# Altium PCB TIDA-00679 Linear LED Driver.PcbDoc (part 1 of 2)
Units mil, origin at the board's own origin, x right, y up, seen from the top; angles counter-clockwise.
Board outline 4400 x 2430 mil, 2 copper layers (Top Layer, Bottom Layer), stack 62 mil thick; 157 components, 72 nets, 421 pads, 393 vias.
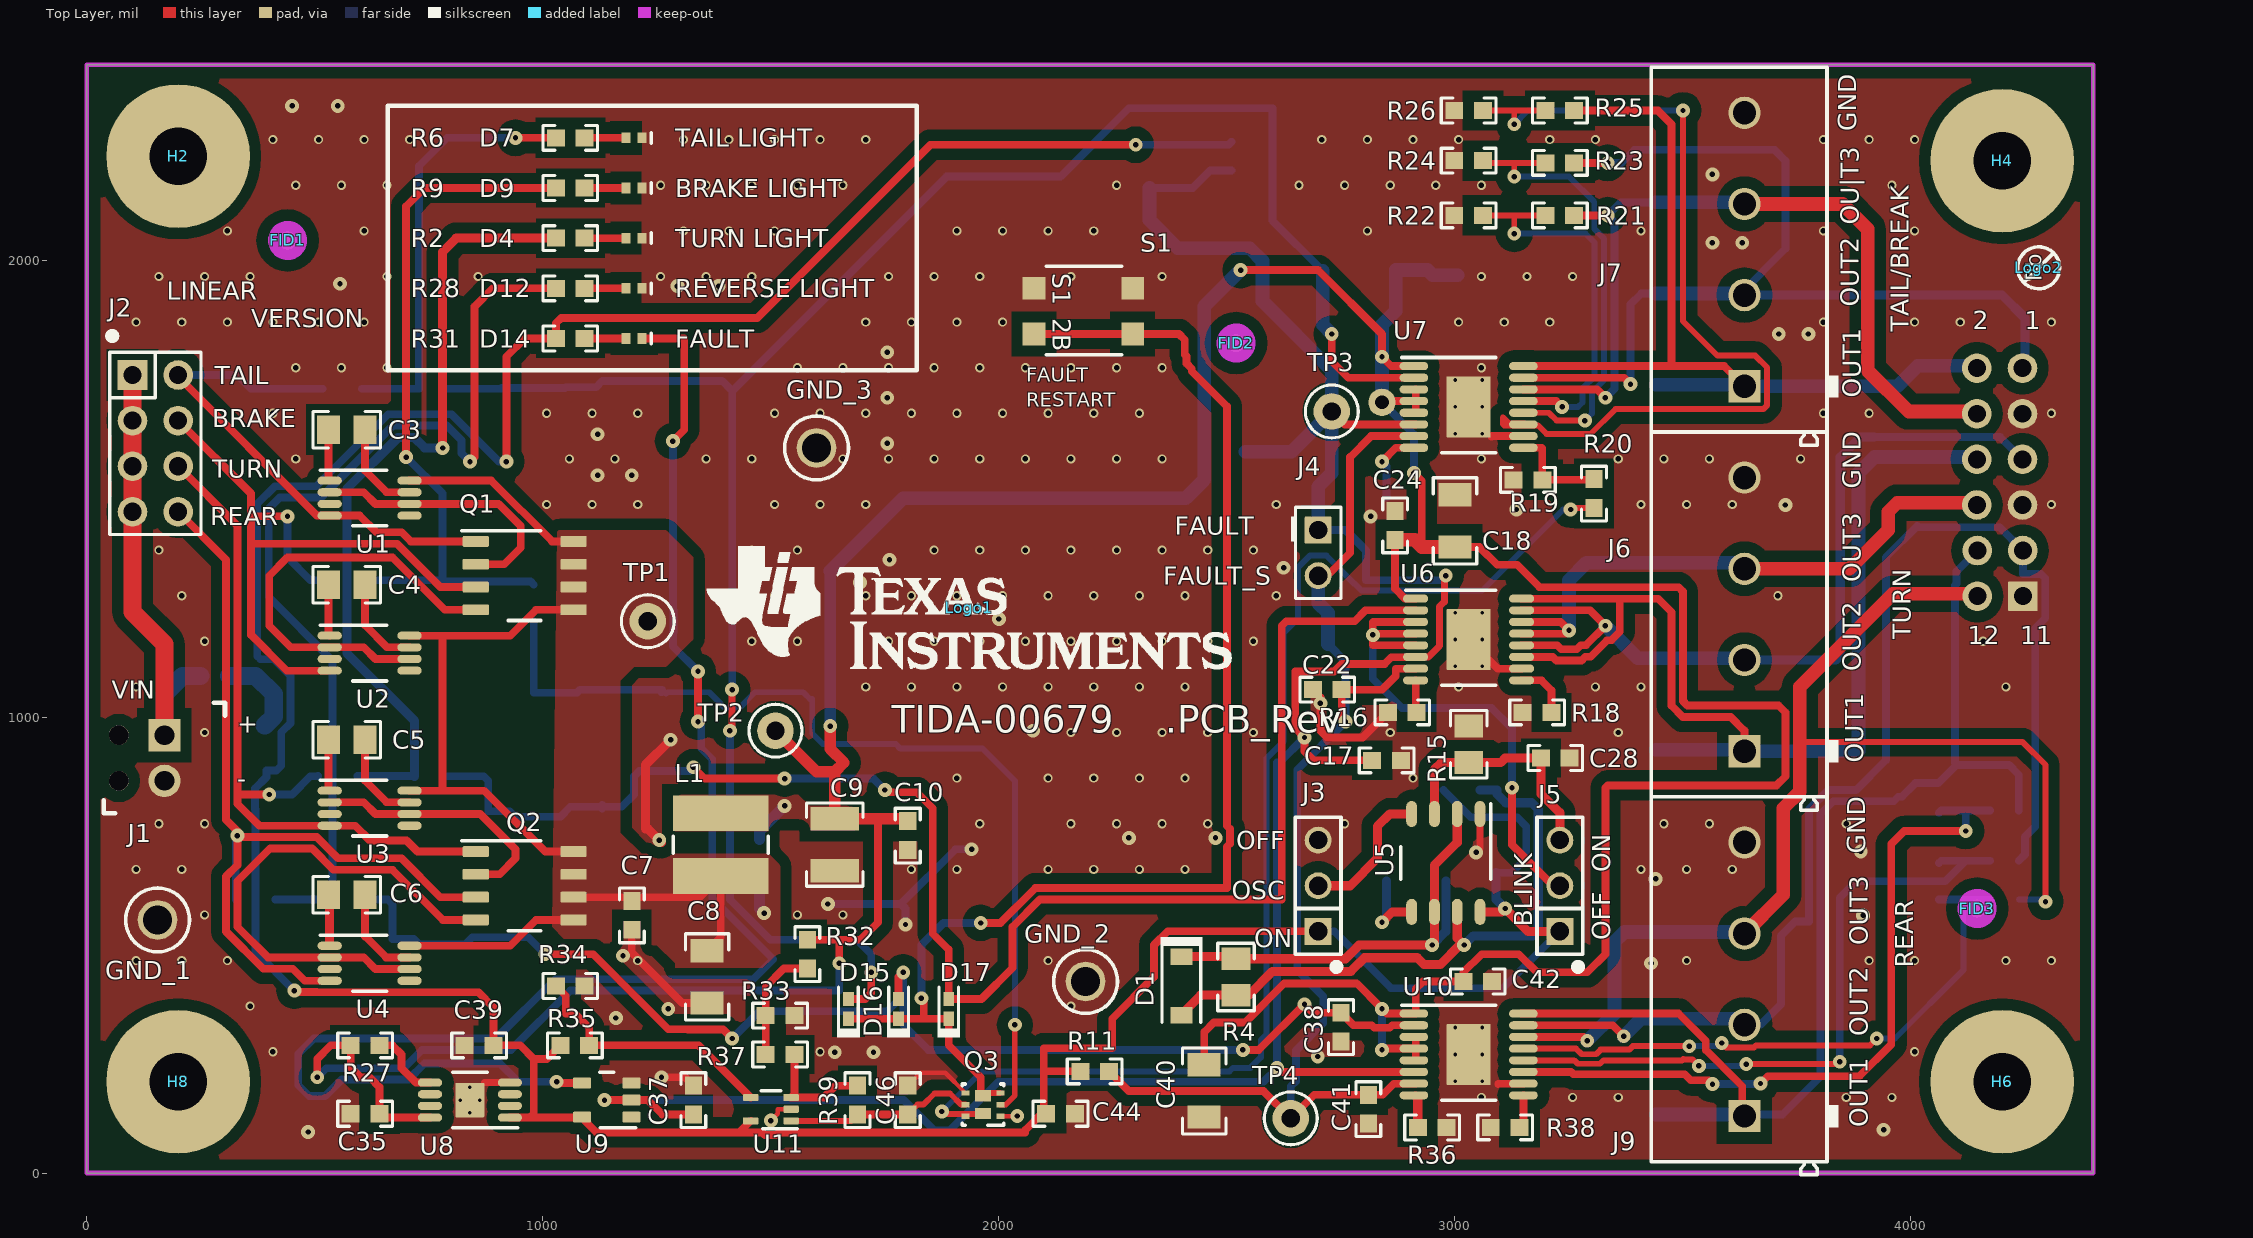
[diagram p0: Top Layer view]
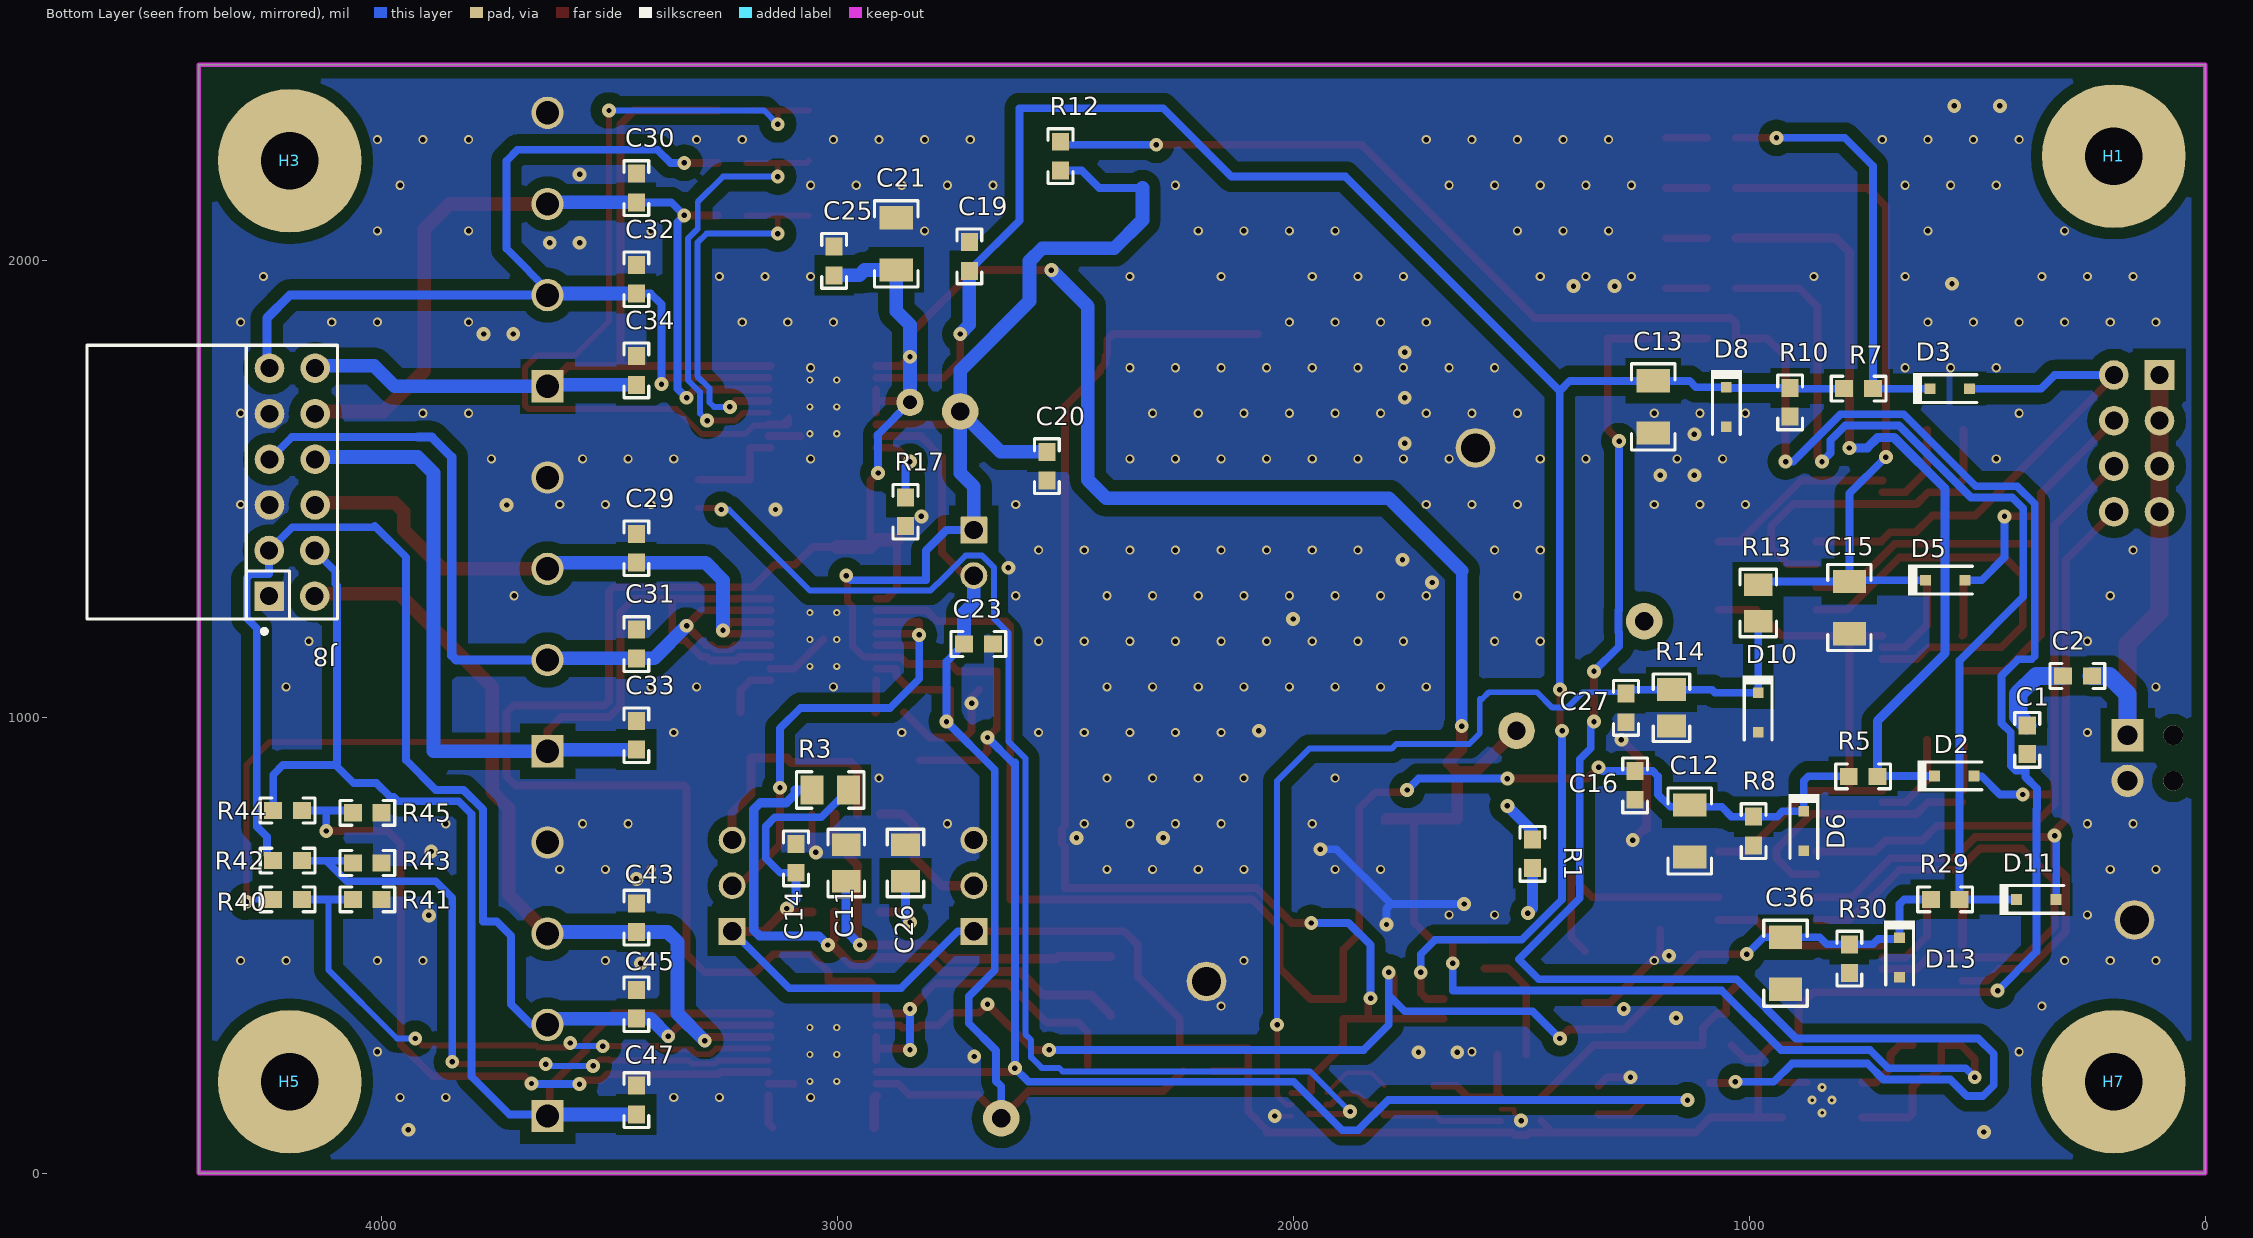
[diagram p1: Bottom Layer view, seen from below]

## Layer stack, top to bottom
Top Solder: solder mask 0.4, Solder Resist, Dk 3.5
Top Layer: signal copper 1.4
Dielectric1: core 59.2, FR-4, Dk 4.8
Bottom Layer: signal copper 1.4
Bottom Solder: solder mask 0.4, Solder Resist, Dk 3.5

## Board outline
0,0 4400,0 4400,2430 0,2430

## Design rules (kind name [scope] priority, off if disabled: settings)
AcuteAngle [All] p1: minimum=4.50000000000000E+0001 checktracksonly=FALSE
AssemblyTestPointUsage [All] p1: valid=2
Clearance Clearance_Keepouts [((IsTrack Or IsArc) And Not InPoly) And IsFree and IsKeepOut vs ((IsTrack Or IsArc) And Not InPoly) And IsFree and IsKeepOut] p1: gap=0
Clearance Clearance_BoardEdge_MountingHoles [OnCopper and InComponentClass('Mounting Holes') vs IsKeepOut] p2: gap=30
Clearance Clearance_BoardEdge_Poly [OnCopper and InPoly vs IsKeepOut] p3: gap=25
Clearance Clearance_BoardEdge [OnCopper and Not InComponentClass('Logo') and not InComponentClass('FiducialMark') and not InRegion(1000,500,4000,800) and Not IsKeepout vs IsKeepOut] p4: gap=60
Clearance Clearance_Poly [InPolygon] p5: gap=25
Clearance [All] p6: gap=7.87
ComponentClearance ComponentClearance_MountingHoles_FiducialMarks [InComponentClass('Mounting Holes') vs InComponentClass('FiducialMark')] p1: gap=50 collisioncheckmode=3 verticalgap=10 showdistances=FALSE
ComponentClearance ComponentClearance_Shunt [InComponentClass('Header') vs InComponentClass('Shunt')] p2: gap=0 collisioncheckmode=3 verticalgap=0 showdistances=FALSE
ComponentClearance ComponentClearance_Logo [InComponentClass('Logo')] p3: gap=50 collisioncheckmode=3 verticalgap=10 showdistances=FALSE
ComponentClearance ComponentClearance_ScrewToNut [(HasFootprint('NY PMS 440 0025 PH')) vs (HasFootprint('Keystone_1902C'))] p4: gap=5 collisioncheckmode=3 verticalgap=10 showdistances=FALSE
ComponentClearance ComponentClearance_MountingHoles [InComponentClass('Mounting Holes')] p5: gap=30 collisioncheckmode=3 verticalgap=100000 showdistances=FALSE
ComponentClearance ComponentClearance_SmallPassives [HasFootprint('0201*') or HasFootprint('0402*') or HasFootprint('0508') or HasFootprint('0603*') or HasFootprint('0612') or HasFootprint('0805*') or HasFootprint('0815*') or HasFootprint('0830*') or HasFootprint('1206*') or HasFootprint('1210*') or HasFootprint('1808*') or HasFootprint('1812*') or HasFootprint('1825*') or HasFootprint('2010*') or HasFootprint('2220*') or HasFootprint('2225*') or HasFootprint('2512*') or HasFootprint('2728*') or HasFootprint('3518*') vs HasFootprint('0201*') or HasFootprint('0402*') or HasFootprint('0508') or HasFootprint('0603*') or HasFootprint('0612') or HasFootprint('0805*') or HasFootprint('0815*') or HasFootprint('0830*') or HasFootprint('1206*') or HasFootprint('1210*') or HasFootprint('1808*') or HasFootprint('1812*') or HasFootprint('1825*') or HasFootprint('2010*') or HasFootprint('2220*') or HasFootprint('2225*') or HasFootprint('2512*') or HasFootprint('2728*') or HasFootprint('3518*')] p6: gap=20 collisioncheckmode=3 verticalgap=10 showdistances=FALSE
ComponentClearance ComponentClearance_THtoSMT [IsThruComponent vs IsSMTComponent] p7: gap=100 collisioncheckmode=3 verticalgap=30 showdistances=FALSE
ComponentClearance ComponentClearance_THtoTH [IsThruComponent vs IsThruComponent] p8: gap=0 collisioncheckmode=3 verticalgap=0 showdistances=TRUE
ComponentClearance [All] p9: gap=40 collisioncheckmode=3 verticalgap=10 showdistances=FALSE
DiffPairsRouting [All] p1: maxlimit=100 minlimit=10 mostfreqgap=10 toplayer_minwidth=15 toplayer_maxwidth=15 toplayer_prefwidth=15 bottomlayer_minwidth=15 bottomlayer_maxwidth=15 bottomlayer_prefwidth=15 maxuncoupledlength=1000
FabricationTestPointUsage TestPointUsage [All] p1: valid=2 allowmultiple=FALSE
FabricationTestpoint Testpoint [All] p1: side=3 testpointundercomponent=TRUE minsize=40 maxsize=100 preferedsize=60 minholesize=0 maxholesize=40 preferedholesize=32 testpointgrid=1 allowsidetop=TRUE allowsidebottom=TRUE usegrid=TRUE gridtolerance=0.01
FanoutControl Fanout_LCC [IsLCC] p1: bgadir=Out bgaviamode=Centered fanoutstyle=Auto fanoutdirection=Alternating viagrid=1 // Fanout_LCC (Default Rule)
FanoutControl Fanout_BGA [IsBGA] p2: bgadir=Out bgaviamode=Centered fanoutstyle=Auto fanoutdirection=Alternating viagrid=1 // Fanout_BGA (Default Rule)
FanoutControl Fanout_Default [All] p4: bgadir=Out bgaviamode=Centered fanoutstyle=Auto fanoutdirection=Alternating viagrid=1 // Fanout_Default (Default Rule)
FanoutControl Fanout_Small [(CompPinCount < 5)] p5: bgadir=Out bgaviamode=Centered fanoutstyle=Auto fanoutdirection=OutThenIn viagrid=1 // Fanout_Small (Default Rule)
HoleSize [All] p1: absolutevalues=TRUE maxlimit=251 minlimit=7.8 maxpercent=80.000 minpercent=20.000
MinimumAnnularRing MinimumAnnularRing_ThermalPadVias [IsVia and InAnyComponent] p1: minimumring=3
MinimumAnnularRing [All] p2: minimumring=4
MinimumSolderMaskSliver MinimumSolderMaskSliver_Logo [InComponentClass('Logo') vs InComponentClass('Logo')] p1: minsoldermaskwidth=0.7
MinimumSolderMaskSliver [All] p2: minsoldermaskwidth=3.94
PlaneConnect [All] p1: planeconnectstyle=Relief reliefexpansion=10 reliefentries=4 reliefconductorwidth=10 reliefairgap=10
PolygonConnect [All] p1: connectstyle=Direct reliefconductorwidth=10 reliefentries=4 polygonreliefangle="90 Angle" airgapwidth=10
RoutingVias ThermalPadVias [IsVia and InAnyComponent] p1: holewidth=7.8 width=19.68 viastyle="Through Hole" minholewidth=7.8 minwidth=13.8 maxholewidth=12.99 maxwidth=23.62
RoutingVias [All] p2: holewidth=16 width=34 viastyle="Through Hole" minholewidth=7.8 minwidth=20 maxholewidth=40 maxwidth=65
SilkToBoardRegionClearance [Not ((IsComment or IsDesignator) And (Hide <> 'False')) and not InRegion(1000,500,4000,800)] p1:
SilkToSilkClearance SilkToSilkClearance_Pb-FreeLogo [(HasFootprint('Pb-Free_Overlay_Medium') OR HasFootprint('Pb-Free_Overlay_Small')) vs (HasFootprint('Pb-Free_Overlay_Medium') OR HasFootprint('Pb-Free_Overlay_Small'))] p1: silktosilkclearance=0
SilkToSilkClearance [All] p2: silktosilkclearance=0
SilkToSolderMaskClearance SilkToComonentPadClearance [IsPad and InAnycomponent] p1: minsilkscreentomaskgap=0 clearancetoexposedcopper=TRUE
SilkToSolderMaskClearance "Silk to Solder Mask Opening" [All] p2: minsilkscreentomaskgap=0 clearancetoexposedcopper=FALSE
SolderMaskExpansion [All] p1: expansion=1.97
UnpouredPolygon [All] p1: allowunpoured=FALSE
Width [All] p1: maxlimit=100 minlimit=6 preferedwidth=10 checkconnectedcopper=TRUE
14 further rules are at their usual default settings.

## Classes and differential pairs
component class "Mounting Holes": H2 H4 H6 H8
component class Logo: Logo1
component class "TIDA-00679 Linear LED Driver_Hardware": FID1 FID2 FID3 H1 H2 H3 H4 H5 H6 H7 H8 Logo1 Logo2 ZZ1 ZZ2 ZZ3
component class FiducialMark: FID1 FID2 FID3
component class AssemblyNote: ZZ1 ZZ2 ZZ3
component class Header: J2 J3 J4 J5
component class "TIDA-00679 Linear LED Driver 1": C1 C2 C3 C4 C5 C6 C7 C8 C9 C10 J1 J2 L1 Q1 Q2 R1 TP1 TP2 U1 U2 U3 U4
component class "TIDA-00679 Linear LED Driver 2": C11 C12 C13 C14 C15 C16 C17 C18 C19 C20 C21 C22 C23 C24 C25 C26 C27 C28 C29 C30 C31 C32 C33 C34 C35 C36 C37 C38 C39 C40 C41 C42 C43 C44 C45 C46 C47 C56 C60 D1 D2 D3 D4 D5 D6 D7 D8 D9 D10 D11 D12 D13 D14 D15 D16 D17 GND_1 GND_2 GND_3 J3 J4 J5 J6 J7 J8 J9 Q3 R2 R3 R4 R5 R6 R7 R8 R9 R10 R11 R12 R13 R14 R15 R16 R17 R18 R19 R20 R21 R22 R23 R24 R25 R26 R27 R28 R29 R30 R31 R32 R33 R34 R35 R36 R37 R38 R39 R40 R41 R42 R43 R44 R45 S1 TP3 TP4 U5 U6 U7 U8 U9 U10 U11

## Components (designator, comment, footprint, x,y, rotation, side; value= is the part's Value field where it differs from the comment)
C1 "GRM188R71H473KA61D" 0603 390,950 r90 bottom
C2 "GRM188R71H473KA61D" 0603 280,1090 r180 bottom
C3 "C2012X5R1H225K125AB" 0805_HV 570,1630 r180 top
C4 "C2012X5R1H225K125AB" 0805_HV 570,1290 r180 top
C5 "C2012X5R1H225K125AB" 0805_HV 570,950 r180 top
C6 "C2012X5R1H225K125AB" 0805_HV 570,610 r180 top
C7 "GRM188R72A102KA01D" 0603 1195,565 r270 top
C8 "GRM31CR71H475KA12L" 1206 1360,430 r270 top
C9 "GRM32ER71H106KA12L" 1210 1640,720 r270 top
C10 "C1608X7R1H104K080AA" 0603 1800,740 r270 top
C11 "GRM219R71E824KA88D" 0805_HV 2980,680 r90 bottom
C12 "GRM31CR71H475KA12L" 1206 1130,750 r90 bottom
C13 "GRM31CR71H475KA12L" 1206 1210,1680 r90 bottom
C14 "06035C104KAT2A" 0603 3090,690 r270 bottom
C15 "GRM31CR71H475KA12L" 1206 780,1240 r270 bottom
C16 "06035C104KAT2A" 0603 1249.93,850 r90 bottom
C17 "06035C104KAT2A" 0603 2850,905 r0 top
C18 "GRM31CR71H475KA12L" 1206 3000,1430 r270 top
C19 "06035C104KAT2A" 0603 2710,2010 r270 bottom
C20 "06035C104KAT2A" 0603 2540,1550 r270 bottom
C21 "GRM31CR71H475KA12L" 1206 2870,2037.48 r270 bottom
C22 "06035C104KAT2A" 0603 2720,1060 r180 top
C23 "06035C104KAT2A" 0603 2690,1160 r180 bottom
C24 "06035C104KAT2A" 0603 2868.7,1420 r270 top
C25 "06035C104KAT2A" 0603 3006.21,2000 r270 bottom
C26 "0805YC224JAT2A" 0805_HV 2850,680 r90 bottom
C27 "06035C104KAT2A" 0603 1270,1020 r270 bottom
C28 "06031C103JAT2A" 0603 3220,910 r0 top
C29 "06031C103JAT2A" 0603 3440.07,1370 r270 bottom
C30 "06031C103JAT2A" 0603 3440.07,2160 r270 bottom
C31 "06031C103JAT2A" 0603 3440.07,1160 r270 bottom
C32 "06031C103JAT2A" 0603 3440.07,1960 r270 bottom
C33 "06031C103JAT2A" 0603 3440.07,960 r270 bottom
C34 "06031C103JAT2A" 0603 3440,1760 r270 bottom
C35 "C1608X7R1H104K" 0603 610,130 r180 top
C36 "GRM31CR71H475KA12L" 1206 920,460 r90 bottom
C37 "0603YC104JAT2A" 0603 1330,160 r90 top
C38 "06035C104KAT2A" 0603 2750,320 r90 top
C39 "C1608X5R1A226M080AC" 0603 860,280 r180 top
C40 "GRM31CR71H475KA12L" 1206 2450,180 r90 top
C41 "06035C104KAT2A" 0603 2810,140 r270 top
C42 "06035C104KAT2A" 0603 3050,420 r180 top
C43 "06031C103JAT2A" 0603 3440.07,560 r270 bottom
C44 "0603YC104JAT2A" 0603 2135,130 r180 top
C45 "06031C103JAT2A" 0603 3440.07,370 r270 bottom
C46 "0603YC104JAT2A" 0603 1800,160 r270 top
C47 "06031C103JAT2A" 0603 3440.07,160 r270 bottom
D1 "1N4148W-7-F" SOD-123 2400,410 r270 top
D2 "PMEG6010CEJ,115" SOD-323F 550,870.87 r180 bottom
D3 "PMEG6010CEJ,115" SOD-323F 560,1720 r180 bottom
D4 "SML-P12PTT86" SML-P1_GREEN 1200,2050 r180 top
D5 "PMEG6010CEJ,115" SOD-323F 570,1300 r180 bottom
D6 "BZT52C9V1S-7-F" sod-323 880,750 r270 bottom
D7 "SML-P12PTT86" SML-P1_GREEN 1200,2270 r180 top
D8 "BZT52C9V1S-7-F" sod-323 1050,1680 r270 bottom
D9 "SML-P12PTT86" SML-P1_GREEN 1200,2160 r180 top
D10 "MMSZ5229BS-7-F" sod-323 980,1010 r270 bottom
D11 "PMEG6010CEJ,115" SOD-323F 370,600 r180 bottom
D12 "SML-P12PTT86" SML-P1_GREEN 1200,1940 r180 top
D13 "BZT52C9V1S-7-F" sod-323 670,472.8 r270 bottom
D14 "SML-P12UTT86" SML-P1_RED 1200,1830 r180 top
D15 "SBR0220T5-7-F" SOD-523 1670,360 r90 top
D16 "SBR0220T5-7-F" SOD-523 1780,360 r90 top
D17 "SBR0220T5-7-F" SOD-523 1890,360 r90 top
FID1 "Fiducial" Fiducial10-20 440,2045 r0 top
FID2 "Fiducial" Fiducial10-20 2520,1820 r0 top
FID3 "Fiducial" Fiducial10-20 4145.02,580 r0 top
GND_1 "5011" Keystone5011 155,555 r0 top
GND_2 "5011" Keystone5011 2190,420 r0 top
GND_3 "5011" Keystone5011 1600,1590 r0 top
H1 "1902C" Keystone_1902C 200,2230 r180 bottom locked
H2 "NY PMS 440 0025 PH" "NY PMS 440 0025 PH" 200,2230 r0 top locked
H3 "1902C" Keystone_1902C 4200,2220 r180 bottom locked
H4 "NY PMS 440 0025 PH" "NY PMS 440 0025 PH" 4200,2220 r0 top locked
H5 "1902C" Keystone_1902C 4200,200 r180 bottom locked
H6 "NY PMS 440 0025 PH" "NY PMS 440 0025 PH" 4200,200 r0 top locked
H7 "1902C" Keystone_1902C 200,200 r180 bottom locked
H8 "NY PMS 440 0025 PH" "NY PMS 440 0025 PH" 200,200 r0 top locked
J1 "1725656" CONN_1725656 170,910 r270 top
J2 "PEC04DAAN" CONN_PEC04DAAN 150,1600 r270 top
J3 "PEC03SAAN" CONN_PEC03SAAN 2700,630 r90 top
J4 "PEC02SAAN" CONN_PEC02SAAN 2700,1360 r270 top
J5 "PEC03SAAN" CONN_PEC03SAAN 3230,630 r90 top
J6 "1715747" Phoenix_1715747 3634.79,1225 r90 top
J7 "1715747" Phoenix_1715747 3634.79,2025 r90 top
J8 "SSQ-106-02-G-D-RA" SSQ-106-02-G-D-RA 4195,1515 r270 bottom
J9 "1715747" Phoenix_1715747 3634.79,425 r90 top
L1 "74408943022" WE-SPC_4838 1390,720 r90 top
Logo1 "Texas Instruments" TI_Stacked_Overlay_Medium 1935,1240 r0 top
Logo2 "Pb-Free Symbol" Pb-Free_Overlay_Small 4280,1985 r90 top
Q1 "SQ9945BEY-T1-GE3" SOIC-8 960,1310 r0 top
Q2 "SQ9945BEY-T1-GE3" SOIC-8 960,630 r0 top
Q3 "CSD85301Q2" DQK0006B 1965,150 r180 top
R1 "RC0603JR-070RL" 0603 1475,700 r90 bottom
R2 "CRCW06033K30JNEA" 0603 1060,2050 r180 top
R3 "CRCW0805680KJNEA" 0805_HV 3014.61,839.88 r180 bottom
R4 "CRCW0805680KJNEA" 0805_HV 2520,430 r270 top
R5 "RC0603FR-0759KL" 0603 750,870 r0 bottom
R6 "CRCW06033K30JNEA" 0603 1060,2270 r180 top
R7 "RC0603FR-0759KL" 0603 760,1720 r0 bottom
R8 "RC0603FR-0742K2L" 0603 990,750 r90 bottom
R9 "CRCW06033K30JNEA" 0603 1060,2160 r180 top
R10 "RC0603FR-0742K2L" 0603 910,1690 r90 bottom
R11 "CRCW0603100KFKEA" 0603 2210,222.97 r180 top
R12 "CRCW0603100KFKEA" 0603 2509.93,2230 r90 bottom
R13 "CRCW080521K5FKEA" 0805_HV 980,1250 r90 bottom
R14 "CRCW080520K0JNEA" 0805_HV 1170,1020 r90 bottom
R15 "CRCW0805100KFKEA" 0805_HV 3030,940 r270 top
R16 "CRCW06030000Z0EA" 0603 2884.43,1010 r0 top
R17 "CRCW06030000Z0EA" 0603 2850,1450 r90 bottom
R18 "CRCW06031K21FKEA" 0603 3180,1010 r0 top
R19 "CRCW06031K21FKEA" 0603 3160,1520 r0 top
R20 "CRCW06032K43FKEA" 0603 3305,1490 r90 top
R21 "CRCW06030000Z0EA" 0603 3230,2100 r0 top
R22 "CRCW060320K0FKEA" 0603 3030,2100 r0 top
R23 "CRCW06030000Z0EA" 0603 3230,2215 r0 top
R24 "CRCW060320K0FKEA" 0603 3030,2220 r0 top
R25 "CRCW06030000Z0EA" 0603 3230,2330 r0 top
R26 "CRCW060320K0FKEA" 0603 3030,2330 r0 top
R27 "CRCW060310K0FKEA" 0603 610,280 r180 top
R28 "CRCW06033K30JNEA" 0603 1060,1940 r180 top
R29 "RC0603FR-0759KL" 0603 570,600 r0 bottom
R30 "RC0603FR-0742K2L" 0603 780,470 r90 bottom
R31 "RC0603FR-07470RL" 0603 1060,1830 r180 top
R32 "CRCW06035K62FKEA" 0603 1580,480 r90 top
R33 "RC0603FR-07510RL" 0603 1520,345 r180 top
R34 "CRCW060310K0FKEA" 0603 1070,280 r180 top
R35 "CRCW060310K0FKEA" 0603 1060,410 r180 top
R36 "CRCW06030000Z0EA" 0603 2950,100 r180 top
R37 "RC0603FR-072K55L" 0603 1520,260 r0 top
R38 "CRCW06031K21FKEA" 0603 3110,100 r0 top
R39 "RC0603FR-0747KL" 0603 1690,160 r90 top
R40 "CRCW06030000Z0EA" 0603 4205,600 r0 bottom
R41 "CRCW060320K0FKEA" 0603 4030,600 r0 bottom
R42 "CRCW06030000Z0EA" 0603 4205,685 r0 bottom
R43 "CRCW060320K0FKEA" 0603 4030,680 r0 bottom
R44 "CRCW06030000Z0EA" 0603 4205,795 r0 bottom
R45 "CRCW060320K0FKEA" 0603 4030,790 r0 bottom
S1 "7914G-1-000E" SW_7914G-1-000E 2185,1890 r270 top
TP1 "5000" Keystone5000 1230,1210 r0 top
TP2 "5000" Keystone5000 1510,970 r0 top
TP3 "5000" Keystone5000 2730,1670 r0 top
TP4 "5000" Keystone5000 2640,120 r0 top
U1 "LM74610QDGKRQ1" DGK0008A_N 620,1480 r0 top
U2 "LM74610QDGKRQ1" DGK0008A_N 620,1140 r0 top
U3 "LM74610QDGKRQ1" DGK0008A_N 620,800 r0 top
U4 "LM74610QDGKRQ1" DGK0008A_N 620,460 r0 top
U5 "TLC555CD" D0008A_N 2980,680 r270 top
U6 "TPS92630QPWPRQ1" PWP0016F_N 3030,1170 r0 top
U7 "TPS92630QPWPRQ1" PWP0016F_M 3030,1680 r0 top
U8 "TPS7A1633QDGNRQ1" DGN0008C_N 840,160 r180 top
U9 "SN74LVC1G07DBVR" DBV0005A_N 1140,160 r180 top
U10 "TPS92630QPWPRQ1" PWP0016F_M 3030,260 r0 top
U11 "LMV7239QM7" DCK0005A_N 1500,140 r180 top
ZZ1 "This Assembly Note will show in the PcbDoc and associated outputs" AssemblyNote 185,3829.11 r0 top
ZZ2 "This Assembly Note will show in the PcbDoc and associated outputs" AssemblyNote 185,3740.56 r0 top
ZZ3 "This Assembly Note will show in the PcbDoc and associated outputs" AssemblyNote 185,3652 r0 top

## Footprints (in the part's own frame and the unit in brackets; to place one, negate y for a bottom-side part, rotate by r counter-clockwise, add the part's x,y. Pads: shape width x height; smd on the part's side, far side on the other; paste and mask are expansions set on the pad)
0603 [mm] "0603 from SM-752 data"
  rect 1x0.95 smd: 1(-0.8,0) 2(0.8,0)
  silkscreen extent -1.52,-0.69 1.52,0.69, body extent -0.87,-0.47 0.87,0.47, height 1
0805_HV [mil] "0805 with 30mil clearance between pads"
  rect 50x63 smd: 1(-40,0) 2(40,0)
  silkscreen extent -74,-40 74,40, body extent -43,-29 43,29, height 57
1206 [mm] "1206 from SM-752 data"
  rect 1.3x1.85 smd: 1(-1.45,0) 2(1.45,0)
  silkscreen extent -2.4,-1.21 2.4,1.21, body extent -1.7,-0.9 1.7,0.9, height 1.35
1210 [mm] "1210 from SM-752 data"
  rect 1.3x2.7 smd: 1(-1.45,0) 2(1.45,0)
  silkscreen extent -2.32,-1.57 2.32,1.57, body extent -1.7,-1.35 1.7,1.35, height 1.35
AssemblyNote [mil] "Assembly Note"
CONN_1725656 [mm] "Phoenix Contact"
  rect 1.8x1.8 hole 1.1: 1(-1.27,0)
  round 1.8 hole 1.1: 2(1.27,0)
  round 1.1 hole 1.1 unplated: MH1(-1.275,-2.54) MH2(1.27,-2.54)
  silkscreen extent -3.08,-3.37 3.08,3.37, body extent -2.77,-3.1 2.77,3.1, height 8.52
CONN_PEC02SAAN [mm] "SULLINS"
  rrect7% 1.5x1.5 hole 1.016: 1(-1.27,0)
  round 1.5 hole 1.016: 2(1.27,0)
  silkscreen extent -2.54,-1.52 2.54,1.27, body extent -2.54,-1.27 2.54,1.27, height 8.38
CONN_PEC03SAAN [mm] "SULLINS"
  rect 1.5x1.5 hole 1.016: 1(-2.54,0)
  round 1.5 hole 1.016: 2(0,0) 3(2.54,0)
  silkscreen extent -4.72,-1.27 3.81,1.27, body extent -3.84,-1.3 3.84,1.3, height 8.38
CONN_PEC04DAAN [mm] "SULLINS"
  rect 1.65x1.65 hole 1.016 mask+0: 1(-3.81,-1.27)
  round 1.65 hole 1.016 mask+0: 2(-3.81,1.27) 3(-1.27,-1.27) 4(-1.27,1.27) 5(1.27,-1.27) 6(1.27,1.27) 7(3.81,-1.27) 8(3.81,1.27)
  silkscreen extent -6.18,-2.6 5.08,2.54, body extent -5.08,-2.54 5.08,2.54, height 8.38
D0008A_N [mm] "SOIC, 8-Leads, Body 4.9x3.9mm, Pitch 1.27mm, IPC Medium Density"
  oval 1.45x0.6 smd: 1(-2.725,1.905) 2(-2.725,0.635) 3(-2.725,-0.635) 4(-2.725,-1.905) 5(2.725,-1.905) 6(2.725,-0.635) 7(2.725,0.635) 8(2.725,1.905)
  silkscreen extent -3.3,-2.5 0.9,2.5, body extent -3,-2.45 3,2.45, height 1.63
DBV0005A_N [mm] "SOT23, 5-Leads, Body 2.9x1.6mm, Pitch 0.95mm, Lead Span 2.8mm, IPC Medium Density"
  rrect17% 1x0.6 smd: 1(-1.375,0.95) 2(-1.375,0) 3(-1.375,-0.95) 4(1.375,-0.95) 5(1.375,0.95)
  silkscreen extent -1.63,-1.55 0.38,1.55, body extent -1.42,-1.46 1.42,1.46, height 1.09
DCK0005A_N [mm] "SOT353, 5-Leads, Body 2x1.3mm, Pitch 0.65mm, Lead Span 2.1mm, IPC Medium Density"
  rrect25% 0.85x0.4 smd: 1(-1.125,0.65) 2(-1.125,0) 3(-1.125,-0.65) 4(1.125,-0.65) 5(1.125,0.65)
  silkscreen extent -1.48,-1.02 0.55,1.1, body extent -1.14,-1 1.14,1, height 0.95
DGK0008A_N [mm] "TSOP, 8-Leads, Body 3x3mm, Pitch 0.65mm, IPC Medium Density"
  oval 1.35x0.45 smd: 1(-2.225,0.975) 2(-2.225,0.325) 3(-2.225,-0.325) 4(-2.225,-0.975) 5(2.225,-0.975) 6(2.225,-0.325) 7(2.225,0.325) 8(2.225,0.975)
  silkscreen extent -2.75,-1.55 0.95,1.55, body extent -2.45,-1.5 2.45,1.5, height 0.96
DGN0008C_N [mm] "TSOP, 8-Leads, Body 3x3mm, Pitch 0.65mm, Thermal Pad 1.98x1.88mm, IPC Medium Density"
  rrect100% 1.35x0.45 smd: 1(-2.225,0.975) 2(-2.225,0.325) 3(-2.225,-0.325) 4(-2.225,-0.975) 5(2.225,-0.975) 6(2.225,-0.325) 7(2.225,0.325) 8(2.225,0.975)
  rrect6% 1.6x1.92 smd: 9(0,0)
  silkscreen extent -2.65,-1.55 0.95,1.55, body extent -2.46,-1.5 2.46,1.5, height 1.1
DQK0006B [mm] "TI"
  rect 0.45x0.3 smd: 1(-0.975,0.65) 2(-0.975,0) 3(-0.975,-0.65) 4(0.975,-0.65) 5(0.975,0) 6(0.975,0.65)
  rect 0.9x0.625 smd paste-0.025: 7(0,0.488) 8(0,-0.488)
  silkscreen extent -1.15,-1.15 1.15,1.15, body extent -1.05,-1.05 1.05,1.05, height 0.8
Fiducial10-20 [mm]
  round 1 smd mask+0.5: 1(0,0)
  Top Layer keep-out circle w1.178: c0,0 r0.5
Keystone5000 [mil] "For Keystone 500x miniature loop terminals"
  round 80 hole 40: 1(0,0)
  silkscreen extent -58,-58 58,58, body extent -49,-49 49,49, height 182
Keystone5011 [mil] "Keystone Multipurpose loops"
  round 87 hole 63: 1(0,0)
  silkscreen extent -70,-70 70,70, body extent -63,-63 63,62, height 319
Keystone_1902C [mil] "Hex Standoff, 4-40 threaded, nylon"
  round 1 on Mech4: 0(0,0)
  body extent -145,-126 146,126, height 501
"NY PMS 440 0025 PH" [mm] "4-40 nylon screw and mounting hole"
  round 8 hole 3.2: 1(0,0)
  body extent -3.3,-3.3 3.3,3.3, height 2.69
Pb-Free_Overlay_Small [mil]
  silkscreen extent -46,-46 46,46
Phoenix_1715747 [mm] "Terminal Block, 5.08mm, 4x1, TH"
  rect 1.8x1.8 hole 1.3: 1(-7.62,0)
  round 1.8 hole 1.3: 2(-2.54,0) 3(2.54,0) 4(7.62,0)
  silkscreen extent -10.9,-5.25 10.16,5.2, body extent -10.9,-4.6 10.16,5.2, height 14.2
PWP0016F_M [mm] "TSOP, 16-Leads, Body 5x4.4mm, Pitch 0.65mm, Thermal Pad 2.46x3.4 mm, IPC Low Density"
  rrect100% 1.6x0.45 smd: 1(-3.05,2.275) 2(-3.05,1.625) 3(-3.05,0.975) 4(-3.05,0.325) 5(-3.05,-0.325) 6(-3.05,-0.975) 7(-3.05,-1.625) 8(-3.05,-2.275) 9(3.05,-2.275) 10(3.05,-1.625) 11(3.05,-0.975) 12(3.05,-0.325) 13(3.05,0.325) 14(3.05,0.975) 15(3.05,1.625) 16(3.05,2.275)
  rrect4% 2.46x3.4 smd: 17(0,0)
  silkscreen extent -3.72,-2.55 1.5,2.75, body extent -3.21,-2.5 3.21,2.5, height 1
PWP0016F_N [mm] "TSOP, 16-Leads, Body 5x4.4mm, Pitch 0.65mm, Thermal Pad 2.46x3.4 mm, IPC Medium Density"
  rrect100% 1.4x0.45 smd: 1(-2.95,2.275) 2(-2.95,1.625) 3(-2.95,0.975) 4(-2.95,0.325) 5(-2.95,-0.325) 6(-2.95,-0.975) 7(-2.95,-1.625) 8(-2.95,-2.275) 9(2.95,-2.275) 10(2.95,-1.625) 11(2.95,-0.975) 12(2.95,-0.325) 13(2.95,0.325) 14(2.95,0.975) 15(2.95,1.625) 16(2.95,2.275)
  rrect4% 2.46x3.4 smd: 17(0,0)
  silkscreen extent -3.5,-2.55 1.5,2.75, body extent -3.21,-2.5 3.21,2.5, height 1
SML-P1_GREEN [mm] "ROHM"
  rect 0.5x0.6 smd: 1(-0.45,0) 2(0.45,0)
  silkscreen extent -0.95,-0.3 -0.95,0.3, body extent -0.53,-0.33 0.53,0.33, height 0.25
SML-P1_RED [mm] "ROHM"
  rect 0.5x0.6 smd: 1(-0.45,0) 2(0.45,0)
  silkscreen extent -0.95,-0.3 -0.95,0.3, body extent -0.52,-0.33 0.52,0.33, height 0.25
SOD-123 [mm] "On Semi recommended land pattern"
  rect 0.915x1.22 smd: 1(-1.637,0) 2(1.637,0)
  silkscreen extent -2.74,-1.17 2.03,1.17, body extent -1.93,-0.9 1.93,0.9, height 1.35
sod-323 [mm] "NXP recommended land pattern"
  rect 0.6x0.6 smd paste-0.05: 1(-1.1,0) 2(1.1,0)
  silkscreen extent -2.06,-0.86 1.53,0.86, body extent -1.3,-0.67 1.3,0.68, height 1.1
SOD-323F [mm] "NXP recommended land pattern"
  rect 0.6x0.6 smd paste-0.05: 1(-1.1,0) 2(1.1,0)
  silkscreen extent -2.06,-0.86 1.53,0.86, body extent -1.35,-0.67 1.35,0.67, height 0.79
SOD-523 [mm] "NXP Semiconductor recommended land pattern, nominal STEP model"
  rect 0.8x0.6 smd paste-0.05: 1(-0.55,0) 2(0.55,0)
  silkscreen extent -1.6,-0.64 1.2,0.63, body extent -0.8,-0.4 0.8,0.4, height 0.72
SOIC-8 [mm] "duplicate of SO-8.  SOIC, 8-Leads, Body 5.0x4.0mm (max), Pitch 1.27mm, IPC Medium Density"
  rrect17% 1.45x0.6 smd: 1(-2.725,1.905) 2(-2.725,0.635) 3(-2.725,-0.635) 4(-2.725,-1.905) 5(2.725,-1.905) 6(2.725,-0.635) 7(2.725,0.635) 8(2.725,1.905)
  silkscreen extent -3.5,-2.5 0.9,2.5, body extent -3,-2.45 3,2.45, height 1.63
SSQ-106-02-G-D-RA [mm] "Samtec Right Angle Header"
  rrect6% 1.65x1.65 hole 1: 1(6.35,-1.283)
  round 1.65 hole 1: 2(6.35,1.257) 3(3.81,-1.283) 4(3.81,1.257) 5(1.27,-1.257) 6(1.27,1.283) 7(-1.27,-1.257) 8(-1.27,1.283) 9(-3.81,-1.257) 10(-3.81,1.283) 11(-6.35,-1.257) 12(-6.35,1.283)
  silkscreen extent -7.62,-11.43 8.43,2.53, body extent -7.62,-11.29 7.62,1.6, height 5.08
SW_7914G-1-000E [mm] "BOURNS"
  rect 1.27x1.27 smd: 1(-1.27,2.75) 2(-1.27,-2.75) 3(1.27,-2.75) 4(1.27,2.75)
  silkscreen extent -2.49,-2.06 2.44,2.14, body extent -2.5,-3.1 2.5,3.1, height 4.13
TI_Stacked_Overlay_Medium [mil]
  silkscreen extent -576,-136 576,134
WE-SPC_4838 [mm] "WURTH"
  rect 2x5.3 smd: 1(-1.75,0) 2(1.75,0)
  silkscreen extent -0.48,-2.65 0.48,2.65, body extent -2.55,-2.55 2.55,2.55, height 4.1

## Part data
C1 C2: "CAP, CERM, 0.047 µF, 50 V, +/- 10%, X7R, 0603"
C3 C4 C5 C6: "CAP, CERM, 2.2 µF, 50 V, +/- 10%, X5R, 0805"
C7: "CAP, CERM, 1000 pF, 100 V, +/- 10%, X7R, 0603"
C8 C12 C13 C15 C18 C21 C36 C40: "CAP, CERM, 4.7 µF, 50 V, +/- 10%, X7R, 1206"
C9: "CAP, CERM, 10 µF, 50 V, +/- 10%, X7R, 1210"
C10 C14 C16 C17 C19 C20 C22 C23 C24 C25 C27 C35 C38 C41 C42: "CAP, CERM, 0.1 µF, 50 V, +/- 10%, X7R, 0603"
C11: "CAP, CERM, 0.82 µF, 25 V, +/- 10%, X7R, 0805"
C26: "CAP, CERM, 0.22 µF, 16 V, +/- 5%, X7R, 0805"
C28 C29 C30 C31 C32 C33 C34 C43 C45 C47: "CAP, CERM, 0.01 µF, 100 V, +/- 5%, X7R, 0603"
C37 C44 C46: "CAP, CERM, 0.1 µF, 16 V, +/- 5%, X7R, 0603"
C39: "CAP, CERM, 22 µF, 10 V, +/- 20%, X5R, 0603"
D1: "Diode, Ultrafast, 100 V, 0.15 A, SOD-123"
D2 D3 D5 D11: "Diode, Schottky, 60 V, 1 A, SOD-323F"
D4 D7 D9 D12: "LED, Green, SMD"
D6 D8 D13: "Diode, Zener, 9.1 V, 200 mW, SOD-323"
D10: "Diode, Zener, 4.3 V, 200 mW, SOD-323"
D14: "LED, Red, SMD"
D15 D16 D17: "Diode, Schottky, 20 V, 0.2 A, SOD-523"
FID1 FID2 FID3: "Fiducial mark.  There is nothing to buy or mount."
GND_1 GND_2 GND_3: "Test Point, Multipurpose, Black, TH"
H1 H3 H5 H7: "Standoff, Hex, 0.5\"L #4-40 Nylon"
H2 H4 H6 H8: "Machine Screw, Round, #4-40 x 1/4, Nylon, Philips panhead"
J1: "Terminal Block, 100mil, 2x1, 6A, 63V, TH"
J2: "Header, 100mil, 4x2, Tin, TH"
J3 J5: "Header, 100mil, 3x1, Tin, TH"
J4: "Header, 100mil, 2x1, Tin, TH"
J6 J7 J9: "Terminal Block, 5.08mm, 4x1, TH"
J8: "Receptacle, 100mil, 6x2, Gold, R/A, TH"
L1: "Inductor, Shielded Drum Core, Ferrite, 2.2 µH, 3 A, 0.026 ohm, SMD"
Logo1: library part TI_Logo, "Texas Instrument Corporate Signature"
Logo2: library part Pb-Free
Q1 Q2: "MOSFET, N-CH, 60 V, 5.4 A, SOIC-8"
Q3: "MOSFET, N-CH, 20 V, 6.7 A, DQK0006B"
R1 R16 R17 R21 R23 R25 R36 R40 R42 R44: "RES, 0, 5%, 0.1 W, 0603"
R2 R6 R9 R28: "RES, 3.3 k, 5%, 0.1 W, 0603"
R3 R4: "RES, 680 k, 5%, 0.125 W, 0805"
R5 R7 R29: "RES, 59.0 k, 1%, 0.1 W, 0603"
R8 R10 R30: "RES, 42.2 k, 1%, 0.1 W, 0603"
R11 R12: "RES, 100 k, 1%, 0.1 W, 0603"
R13: "RES, 21.5 k, 1%, 0.125 W, 0805"
R14: "RES, 20 k, 5%, 0.125 W, 0805"
R15: "RES, 100 k, 1%, 0.125 W, 0805"
R18 R19 R38: "RES, 1.21 k, 1%, 0.1 W, 0603"
R20: "RES, 2.43 k, 1%, 0.1 W, 0603"
R22 R24 R26 R41 R43 R45: "RES, 20.0 k, 1%, 0.1 W, 0603"
R27 R34 R35: "RES, 10.0 k, 1%, 0.1 W, 0603"
R31: "RES, 470, 1%, 0.1 W, 0603"
R32: "RES, 5.62 k, 1%, 0.1 W, 0603"
R33: "RES, 510, 1%, 0.1 W, 0603"
R37: "RES, 2.55 k, 1%, 0.1 W, 0603"
R39: "RES, 47.0 k, 1%, 0.1 W, 0603"
S1: "Switch, Tactile, SPST-NO, 0.1A, 16V, SMT"
TP1 TP2 TP3 TP4: "Test Point, Miniature, Red, TH"
U1 U2 U3 U4: "Smart Diode Controller, DGK0008A"
U5: "LinCMOS Timer, D0008A"
U6 U7 U10: "Three-Channel Linear LED Driver with Analog and PWM Dimming, PWP0016F"
U8: "60-V, 5-µA IQ, 100-mA, Low-Dropout VOLTAGE REGULATOR With Enable and Power-Good, DGN0008C"
U9: "SINGLE BUFFER/DRIVER WITH OPEN-DRAIN OUTPUT, DBV0005A"
U11: "Automotive 75 nsec, 2.7V to 5V comparator with Rail-to-Rail Input and Output, DCK0005A"
ZZ1 ZZ2 ZZ3: library part AssemblyNote

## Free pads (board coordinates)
  round 60 hole 30: 0(2840,1690)

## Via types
v1: diameter 20, hole 12, Top Layer to Bottom Layer, tented both sides, 246 vias
v2: diameter 30.32, hole 11.81, Top Layer to Bottom Layer, tented both sides, 123 vias
v3: diameter 15.75, hole 7.87, Top Layer to Bottom Layer, 18 vias
v4: diameter 19.68, hole 7.87, Top Layer to Bottom Layer, 4 vias
v5: diameter 30.32, hole 11.81, Top Layer to Bottom Layer, 2 vias

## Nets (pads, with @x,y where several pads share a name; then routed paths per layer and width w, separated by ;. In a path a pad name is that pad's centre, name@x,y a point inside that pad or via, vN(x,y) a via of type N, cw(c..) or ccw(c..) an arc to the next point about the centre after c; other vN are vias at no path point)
3.3V: C14.2 C39.1 C44.2 J3.1 J5.1 R3.2 R11.2 R12.2 R31.2 R34.2 U5.8 U8.1 U9.5 U11.5 | length 8274.5
  Top Layer w17: v2@455,396.74 503.88,396.74 504.23,396.38 858.62,396.38 891.5,363.5 C39.1@891.5,280 950,280 980,250 ; v2(920,1560) 920,1790 960,1830 R31.2@1028.5,1830 1028.5,1863.5 1040,1875 1470,1875 1850,2255 v2(2300,2255) ; U8.1@927.6,121.61 971.61,121.61 ; R34.2@1038.5,280 1008.5,250 980,250 ; U11.5@1455.71,114.41 1430.43,89.13 ; R11.2@2178.5,222.97 2100.53,222.97 2098.5,225 ; J3.1@2700,530 2370,530 2340,500 2340,430 2248.5,338.5 2248.5,273.5 2098.5,273.5 2098.5,225 ; 971.61,121.61 980,130 980,250 ; 971.61,121.61 1084.88,121.61 1117.36,89.13 1430.43,89.13 ; 1430.43,89.13 1481.27,89.13 1486.94,83.47 1513.06,83.47 1518.73,89.13 2057.64,89.13 2057.64,94.13 2098.5,135 2098.5,225
  Top Layer w20: U5.8@3055,572.72 3102.72,572.72 v2(3110,580) 3160,530 J5.1@3230,530
  Bottom Layer w17: v2(455,400) 370,485 370,796.94 368.47,798.47 368.47,843.06 393.93,868.53 393.93,882.44 415.48,882.44 426.37,893.34 426.37,966.43 446.37,986.43 446.37,1090.07 410.07,1126.37 380.92,1126.37 373.75,1133.54 373.75,1467.44 412.56,1506.25 503.14,1506.25 661.01,1664.12 799.57,1664.12 903.69,1560 v2(920,1560) ; v2(2300,2255) 2503.44,2255 R12.2@2509.93,2261.5 ; J3.1@2700,530 2735,530 2860,405 3105,405 J5.1@3230,530 ; R3.2@2974.61,839.88 3034.49,780 3136.22,780 3156.22,760 3156.22,690 3124.73,658.5 C14.2@3090,658.5
  Bottom Layer w20: C14.2@3090,658.5 3090,600 v2(3110,580)
/FAULT: C17.1 C20.1 C37.1 J4.1 R12.1 TP3.1 U6.6 U7.6 U9.2 U10.6 | length 5661.3
  Top Layer w15: U6.6@2913.86,1131.61 2941.61,1131.61 2966.2,1156.2 2966.2,1242.16 2976.34,1252.3 2977.3,1252.3 2977.3,1307.3 v2(2980,1310)
  Top Layer w17: v2(1135,160) U9.2@1194.13,160 1230,160 1261.5,128.5 C37.1@1330,128.5 ; v2@2618.39,221.61 U10.6@2909.92,221.61 U10.6@2913.86,221.61 ; TP3.1@2730,1670 2758.39,1641.61 U7.6@2913.86,1641.61 ; C17.1@2818.5,905 2690,905 2670,925 v2(2670,955) 2650,975 2650,1100 2735,1100 2751.5,1116.5 2845.9,1116.5 2860.66,1131.26 2913.5,1131.26 U6.6@2913.86,1131.61
  Bottom Layer w17: v2(1135,160) 1791.49,160 1857.86,93.63 1892.14,93.63 1998.61,200.1 2580.1,200.1 v2(2610,230) 2610,900 2615,900 v2(2670,955) ; 2330,2160 2425,2160 2463.5,2198.5 R12.1@2509.93,2198.5 ; J4.1@2700,1410 2760,1410 2805,1365 2805,1300 2970,1300 v2(2980,1310)
  Bottom Layer w30: 2330,2160 2330,2090 2392.13,2027.87 2549.83,2027.87 2577.87,1999.83 2577.87,1912.13 2730,1760 TP3.1@2730,1670 ; C20.1@2540,1581.5 2641.5,1581.5 TP3.1@2730,1670 ; J4.1@2700,1410 2700,1505 2730,1535 TP3.1@2730,1670
/FAULT_S: C22.1 C23.1 C41.1 J4.2 R11.1 TP4.1 U6.7 U7.7 U10.7 | length 2785.6
  Top Layer w17: R11.1@2241.5,222.97 2284.47,180 2580,180 TP4.1@2640,120 2691.5,171.5 C41.1@2810,171.5 2841.5,171.5 2866.02,196.02 U10.7@2913.86,196.02 ; J4.2@2700,1310 2720,1310 2770,1360 2770,1570 2816.02,1616.02 U7.7@2913.86,1616.02 ; v2(2760,990) 2751.5,998.5 C22.1@2751.5,1060 2840,1060 2869.93,1089.93 2869.93,1105.34 2870.25,1105.67 U6.7@2913.5,1105.67
  Bottom Layer w17: TP4.1@2640,120 2640,190.11 2651.37,201.49 2651.37,268.63 2711.37,328.63 2711.37,387.14 2654.1,444.41 2654.1,884.1 v2(2760,990) 2760,1121.5 C23.1@2721.5,1160
  Bottom Layer w30: J4.2@2700,1310 2700,1250 2721.5,1228.5 C23.1@2721.5,1160
EN1: C13.2 C19.2 D8.1 D15.2 R7.2 R10.2 U7.2 | length 4507.4
  Top Layer w15: v2(1410,970) 1415,975 v2(1415,1060)
  Top Layer w17: D15.2@1670,381.65 1706.65,381.65 1720,395 v2(1720,440) ; v2(2730,1840) 2730,1780 2766.02,1743.98 U7.2@2913.86,1743.98
  Bottom Layer w17: R7.2@791.5,1720 R10.2@911.5,1720 ; R10.2@910,1721.5 1048.19,1721.5 D8.1@1050,1723.31 1116.69,1723.31 1130.47,1737.09 C13.2@1210,1737.09 1392.91,1737.09 1415,1715 ; v2(1410,970) 1410,600 1498.5,511.5 1688.5,511.5 1720,480 v2(1720,440) ; v2(1415,1060) 1415,1715 ; C19.2@2710,1978.5 2600,2088.5 2600,2335 2285,2335 2135,2185 1885,2185 1415,1715
  Bottom Layer w30: C19.2@2710,1978.5 2710,1860 v2(2730,1840)
EN2: C36.2 C38.2 D13.1 D16.2 R29.2 R30.2 U10.2 | length 2801.1
  Top Layer w17: v2(1005,480) 1110,480 1274.93,315.07 1317.96,315.07 1318.04,315 1395,315 v2(1415,295) ; D16.2@1780,381.65 1780,430 v2(1790,440) ; v2(2535,270) 2570,270 v2(2670,370) 2688.5,351.5 C38.2@2750,351.5 2777.52,323.98 2817.51,323.98 2822.86,318.63 2857.14,318.63 2862.49,323.98 U10.2@2913.86,323.98
  Bottom Layer w17: R29.2@601.5,600 660,600 670,590 670,513.31 716.69,513.31 728.5,501.5 R30.2@780,501.5 829.76,501.5 845.35,517.09 C36.2@920,517.09 967.91,517.09 v2(1005,480) ; v2(1415,295) 1475,355 1755,355 1790,390 ; v2(1790,440) 1790,390 ; v2(2535,270) 1845,270 1790,325 1790,390
EN3: C12.2 C16.2 D6.1 D17.2 R5.2 R8.2 U6.2 | length 3480.4
  Top Layer w17: v2(1330,890) 1355,865 v2(1530,865) ; v2(1750,840) 1755,835 1820,835 1855,800 1855,525 1890,490 D17.2@1890,381.65 1961.65,381.65 2030,450 2030,540 2090,600 2620,600 2620,1200 2630,1210 2780,1210 2803.98,1233.98 U6.2@2913.86,1233.98
  Bottom Layer w17: R5.2@781.5,870 870,870 880,860 D6.1@880,793.31 926.69,793.31 938.5,781.5 R8.2@990,781.5 1038.5,781.5 1060,802.99 C12.2@1134.09,802.99 ; C12.2@1130,798.9 C12.2@1134.09,802.99 ; C12.2@1130,807.09 C12.2@1134.09,802.99 ; v2(1330,890) 1321.5,881.5 C16.2@1249.93,881.5 1211.5,881.5 1200,870 1200,830 1172.99,802.99 C12.2@1134.09,802.99 ; v2(1530,865) 1725,865 v2(1750,840)
KL30_F: C9.1 C10.1 C18.2 C21.2 C24.2 C25.2 C35.1 C40.2 C42.2 L1.2 pad.0 R1.2 R27.2 R32.2 TP2.1 U6.1 U7.1 U7.3 U7.4 U7.5 U8.8 U10.1 U10.3 U10.4 U10.5 | length 9566.4
  Top Layer w17: v2(505,210) 505,250 535,280 R27.2@578.5,280 578.5,231.5 600,210 620,210 641.5,188.5 C35.1@641.5,130 649.88,121.61 U8.8@752.4,121.61 ; R32.2@1580,511.5 1650,511.5 ; v2(1650,460) 1650,511.5 ; 1735,777.09 1735,550 1696.5,511.5 1650,511.5 ; C10.1@1794.41,777.09 C10.1@1800,771.5 ; C40.2@2450,237.09 2450,309 2471,330 2540,330 2625.75,415.75 2784.25,415.75 v2(2840,360) 2850.43,349.57 2913.86,349.57 2913.86,403.86 2930,420 C42.2@3018.5,420 3018.5,439.99 3058.51,480 3140,480 3180,440 3290,440 3330,480 3330,845 3335,850 3705,850 3725,870 3725,1009.67 3709.67,1025 3510,1025 3500,1035 3500,1275 3490.56,1284.44 3185.56,1284.44 3136.37,1333.63 3092.91,1333.63 3053.63,1372.91 C18.2@3000,1372.91 ; v2(2530,1980) 2700,1980 2840,1840 v2(2840,1790) 2860.43,1769.57 U7.1@2913.86,1769.57 ; v2(2840,270) 2842.8,272.8 U10.4@2913.86,272.8 ; pad.0@2840,1690 2842.8,1692.8 U7.4@2913.86,1692.8 ; C24.2@2868.7,1388.5 2868.7,1281.3 2890.43,1259.57 U6.1@2913.86,1259.57 ; v2(2910,1535) 2927.09,1517.91 2927.09,1372.91 ; U10.5@2913.86,247.2 U10.4@2913.86,272.8 ; U10.3@2913.86,298.39 U10.4@2913.86,272.8 ; U7.5@2913.86,1667.2 U7.4@2913.86,1692.8 ; U7.3@2913.86,1718.39 U7.4@2913.86,1692.8
  Top Layer w25: TP2.1@1510,970 1600,880 1640,880 ; v2(1630,980) 1630,930 1660,900 1640,880 ; C10.1@1794.41,777.09 1735,777.09 C9.1@1640,777.09 1640,880
  Top Layer w30: v2(2530,1980) v2@2530.24,1979.76 ; C24.2@2868.7,1388.5 2911.5,1388.5 2927.09,1372.91 C18.2@3000,1372.91
  Bottom Layer w17: v2(505,210) 525,230 695,230 735,270 930,270 1060,400 1650,400 v2(1650,460) ; v2(2840,270) v2(2840,360) ; pad.0@2840,1690 2910,1620 v2(2910,1535)
  Bottom Layer w25: R1.2@1475,731.5 1475,750 v2(1530,805) ; v2(1630,980) 1630,1320
  Bottom Layer w30: 1630,1320 1790,1480 2410,1480 2450,1520 2450,1900 v2(2530,1980) ; pad.0@2840,1690 v2(2840,1790) 2840,1860 2870,1890 C21.2@2870,1980.39 2939.61,1980.39 2951.5,1968.5 C25.2@3006.21,1968.5
NetC1_2: C1.2 C2.1 | length 191.9
  Bottom Layer w40: C2.1@311.5,1090 370,1090 410,1050 410,1001.5 C1.2@390,981.5
NetC2_2: C2.2 J1.1 J2.1 J2.3 J2.5 J2.7 | length 1024.1
  Top Layer w40: J2.1@100,1750 J2.3@100,1650 J2.5@100,1550 J2.7@100,1450 100,1230 170,1160 J1.1@170,950
  Bottom Layer w40: J1.1@170,950 170,1050 210,1090 C2.2@248.5,1090
NetC3_1: C3.1 U1.7 | length 207.2
  Top Layer w17: C3.1@610,1630 610,1540 657.2,1492.8 U1.7@707.6,1492.8
NetC3_2: C3.2 U1.1 | length 112.6
  Top Layer w17: C3.2@530,1630 530,1520.79 U1.1@532.4,1518.39
NetC4_1: C4.1 U2.7 | length 206.6
  Top Layer w17: C4.1@610,1290 610,1201.02 658.23,1152.8 U2.7@707.6,1152.8
NetC4_2: C4.2 U2.1 | length 112.6
  Top Layer w17: C4.2@530,1290 530,1180.79 U2.1@532.4,1178.39
NetC5_1: C5.1 U3.7 | length 207.2
  Top Layer w17: C5.1@610,950 610,860 657.2,812.8 U3.7@707.6,812.8
NetC5_2: C5.2 U3.1 | length 112.6
  Top Layer w17: C5.2@530,950 530,840.79 U3.1@532.4,838.39
NetC6_1: C6.1 U4.7 | length 207.8
  Top Layer w17: C6.1@610,610 610,518.89 656.1,472.8 U4.7@707.6,472.8
NetC6_2: C6.2 U4.1 | length 121.5
  Top Layer w20: C6.2@520,610 C6.2@530,610 532.4,607.6 U4.1@532.4,499.53
NetC7_1: C7.1 C8.1 L1.1 Q1.5 Q1.6 Q1.7 Q1.8 Q2.5 Q2.6 Q2.7 Q2.8 R1.1 TP1.1 U1.8 U2.8 U3.8 U4.8 | length 2557.7
  Top Layer w17: U4.8@707.6,498.39 928.39,498.39 985,555 Q2.5@1067.28,555 ; U3.8@707.6,838.39 778.39,838.39 ; U2.8@707.6,1178.39 780,1178.39 ; U1.8@707.6,1518.39 886.79,1518.39 1020.18,1385 Q1.8@1067.28,1385 ; Q2.6@1067.28,605 1343.9,605 L1.1@1390,651.1 1390,517.09 C8.1@1360,487.09 ; Q2.8@1067.28,705 1005,705 871.61,838.39 778.39,838.39 ; Q1.5@1067.28,1235 985,1235 928.39,1178.39 780,1178.39 ; 778.39,838.39 780,840 780,1178.39
  Bottom Layer w25: R1.1@1475,668.5 1475,580 v2(1485,570)
NetC11_1: C11.1 D1.1 R4.1 U5.2 U5.6 | length 1026.8
  Top Layer w20: D1.1@2400,474.47 2515.53,474.47 R4.1@2520,470 2760,470 2790,500 v2(2950,500) 2955,505 U5.6@2955,572.72 2955,675 3005,725 U5.2@3005,787.28
  Bottom Layer w20: v2(2950,500) 2980,530 C11.1@2980,640
NetC15_1: C15.1 D5.1 R9.2 R13.2 | length 1572
  Top Layer w17: v2(700,1570) 700,2120 740,2160 R9.2@1028.5,2160
  Bottom Layer w17: D5.1@613.31,1300 777.09,1300 C15.1@780,1297.09 ; v2(700,1570) 780,1490 C15.1@780,1297.09 ; R13.2@980,1290 972.91,1297.09 C15.1@780,1297.09
NetC26_1: C26.1 U5.5 | length 168.6
  Top Layer w20: v2(2840,550) 2862.72,572.72 U5.5@2905,572.72
  Bottom Layer w20: v2(2840,550) 2850,560 C26.1@2850,640
NetC27_1: C27.1 D10.1 Q3.2 R13.1 R14.2 | length 2104.9
  Top Layer w12: Q3.2@2003.39,150 2015,150 2035,170 v2(2035,325)
  Top Layer w13: v2(2035,325) v2@2040,320
  Bottom Layer w13: C27.1@1270,1051.5 1272.76,1054.25 1365.06,1054.25 1398.69,1020.63 1431.31,1020.63 1464.94,1054.25 1570.75,1054.25 1585.63,1039.37 1590.63,1039.37 1590.63,963.69 1613.69,940.63 1773.69,940.63 1783.69,930.63 1964.37,930.63 2035,860 v2(2035,325)
  Bottom Layer w17: R13.1@980,1210 D10.1@980,1053.31 1074.76,1053.31 1081.46,1060 R14.2@1170,1060 C27.1@1254.57,1060 ; C27.1@1260.32,1054.25 C27.1@1254.57,1060 ; C27.1@1261.5,1060 C27.1@1254.57,1060
NetC28_1: C28.1 J5.3 R15.2 U5.3 | length 538.8
  Top Layer w20: U5.3@2955,787.28 2955,885 2970,900 R15.2@3030,900 3100,900 3110,910 C28.1@3188.5,910 3188.5,831.5 3230,790 J5.3@3230,730
NetC46_2: C46.2 Q3.5 R39.1 U11.1 | length 417.3
  Top Layer w13: U11.1@1544.29,114.41 1675.91,114.41 R39.1@1690,128.5 ; C46.2@1800,128.5 1821.5,150 1834.32,150 1858.69,174.37 1892.74,174.37 1917.11,150 Q3.5@1926.61,150
  Top Layer w17: R39.1@1690,128.5 C46.2@1800,128.5
NetD1_2: D1.2 R3.1 R4.2 U5.7 | length 1368
  Top Layer w20: D1.2@2400,345.53 2400,347.5 2442.5,390 R4.2@2520,390 2547.87,390 2600,442.13 2771.55,442.13 2801.55,472.13 2917.24,472.13 2932.24,457.13 2967.76,457.13 3010.63,500 v2(3020,500) 3005,515 U5.7@3005,572.72
  Bottom Layer w20: v2(3020,500) 3040,520 3170,520 3182.6,532.6 3182.6,797.4 3168.03,811.97 3111.32,811.97 3091.97,831.32 3091.97,839.88 R3.1@3054.61,839.88
NetD2_1: D2.1 R2.2 R5.1 | length 1774.6
  Top Layer w20: v2(780,1590) 780,2020 810,2050 R2.2@1028.5,2050
  Bottom Layer w17: D2.1@593.31,870.87 717.64,870.87 R5.1@718.5,870
  Bottom Layer w20: R5.1@718.5,870 718.5,991.5 570,1140 570,1500.63 682.24,1612.87 717.76,1612.87 740.63,1590 v2(780,1590)
NetD3_1: D3.1 R6.2 R7.1 | length 939.2
  Top Layer w17: v2(940,2270) R6.2@1028.5,2270
  Bottom Layer w17: D3.1@603.31,1720 R7.1@728.5,1720 728.5,2208.5 790,2270 v2(940,2270)
NetD4_2: D4.2 R2.1 | length 90.8
  Top Layer w17: R2.1@1091.5,2050 D4.2@1182.28,2050
NetD7_2: D7.2 R6.1 | length 90.8
  Top Layer w17: R6.1@1091.5,2270 D7.2@1182.28,2270
NetD9_2: D9.2 R9.1 | length 90.8
  Top Layer w17: R9.1@1091.5,2160 D9.2@1182.28,2160
NetD11_1: D11.1 R28.2 R29.1 | length 2145.8
  Top Layer w17: v2(840,1560) 850,1570 850,1900 890,1940 R28.2@1028.5,1940
  Bottom Layer w17: D11.1@413.31,600 R29.1@538.5,600 538.5,1123.75 398.63,1263.63 398.63,1457.14 422.86,1481.37 513.44,1481.37 671.32,1639.25 789.26,1639.25 821.37,1607.14 821.37,1578.63 v2(840,1560)
NetD12_2: D12.2 R28.1 | length 90.8
  Top Layer w17: R28.1@1091.5,1940 D12.2@1182.28,1940
NetD14_1: D14.1 U9.4 | length 3431.4
  Top Layer w17: v2(1030,200) 1032.6,197.4 U9.4@1085.87,197.4 ; D14.1@1217.72,1830 1310,1830 1310,1630 v2(1285,1605) ; v2(1340,990) v2(1340,1100)
  Bottom Layer w17: v2(1030,200) 945.87,200 905.87,240 740.18,240 705.3,205.13 558.64,205.13 522.14,168.63 487.86,168.63 463.63,192.86 463.63,261.37 497.25,295 897.25,295 1027.12,424.87 1461.1,424.87 1505,468.77 1371.37,602.4 1371.37,907.14 1347.14,931.37 1347.14,982.86 v2(1340,990) ; v2(1285,1605) 1285,1234.72 1286.37,1233.35 1286.37,1186.65 1285,1185.28 1285,1155 v2(1340,1100)
NetD14_2: D14.2 R31.1 | length 90.8
  Top Layer w17: R31.1@1091.5,1830 D14.2@1182.28,1830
